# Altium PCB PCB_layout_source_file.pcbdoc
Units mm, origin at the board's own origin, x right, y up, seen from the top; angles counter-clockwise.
Board outline 87.02 x 77.5 mm, 2 copper layers (Top Layer, Bottom Layer); 64 components, 31 nets, 166 pads, 66 vias.
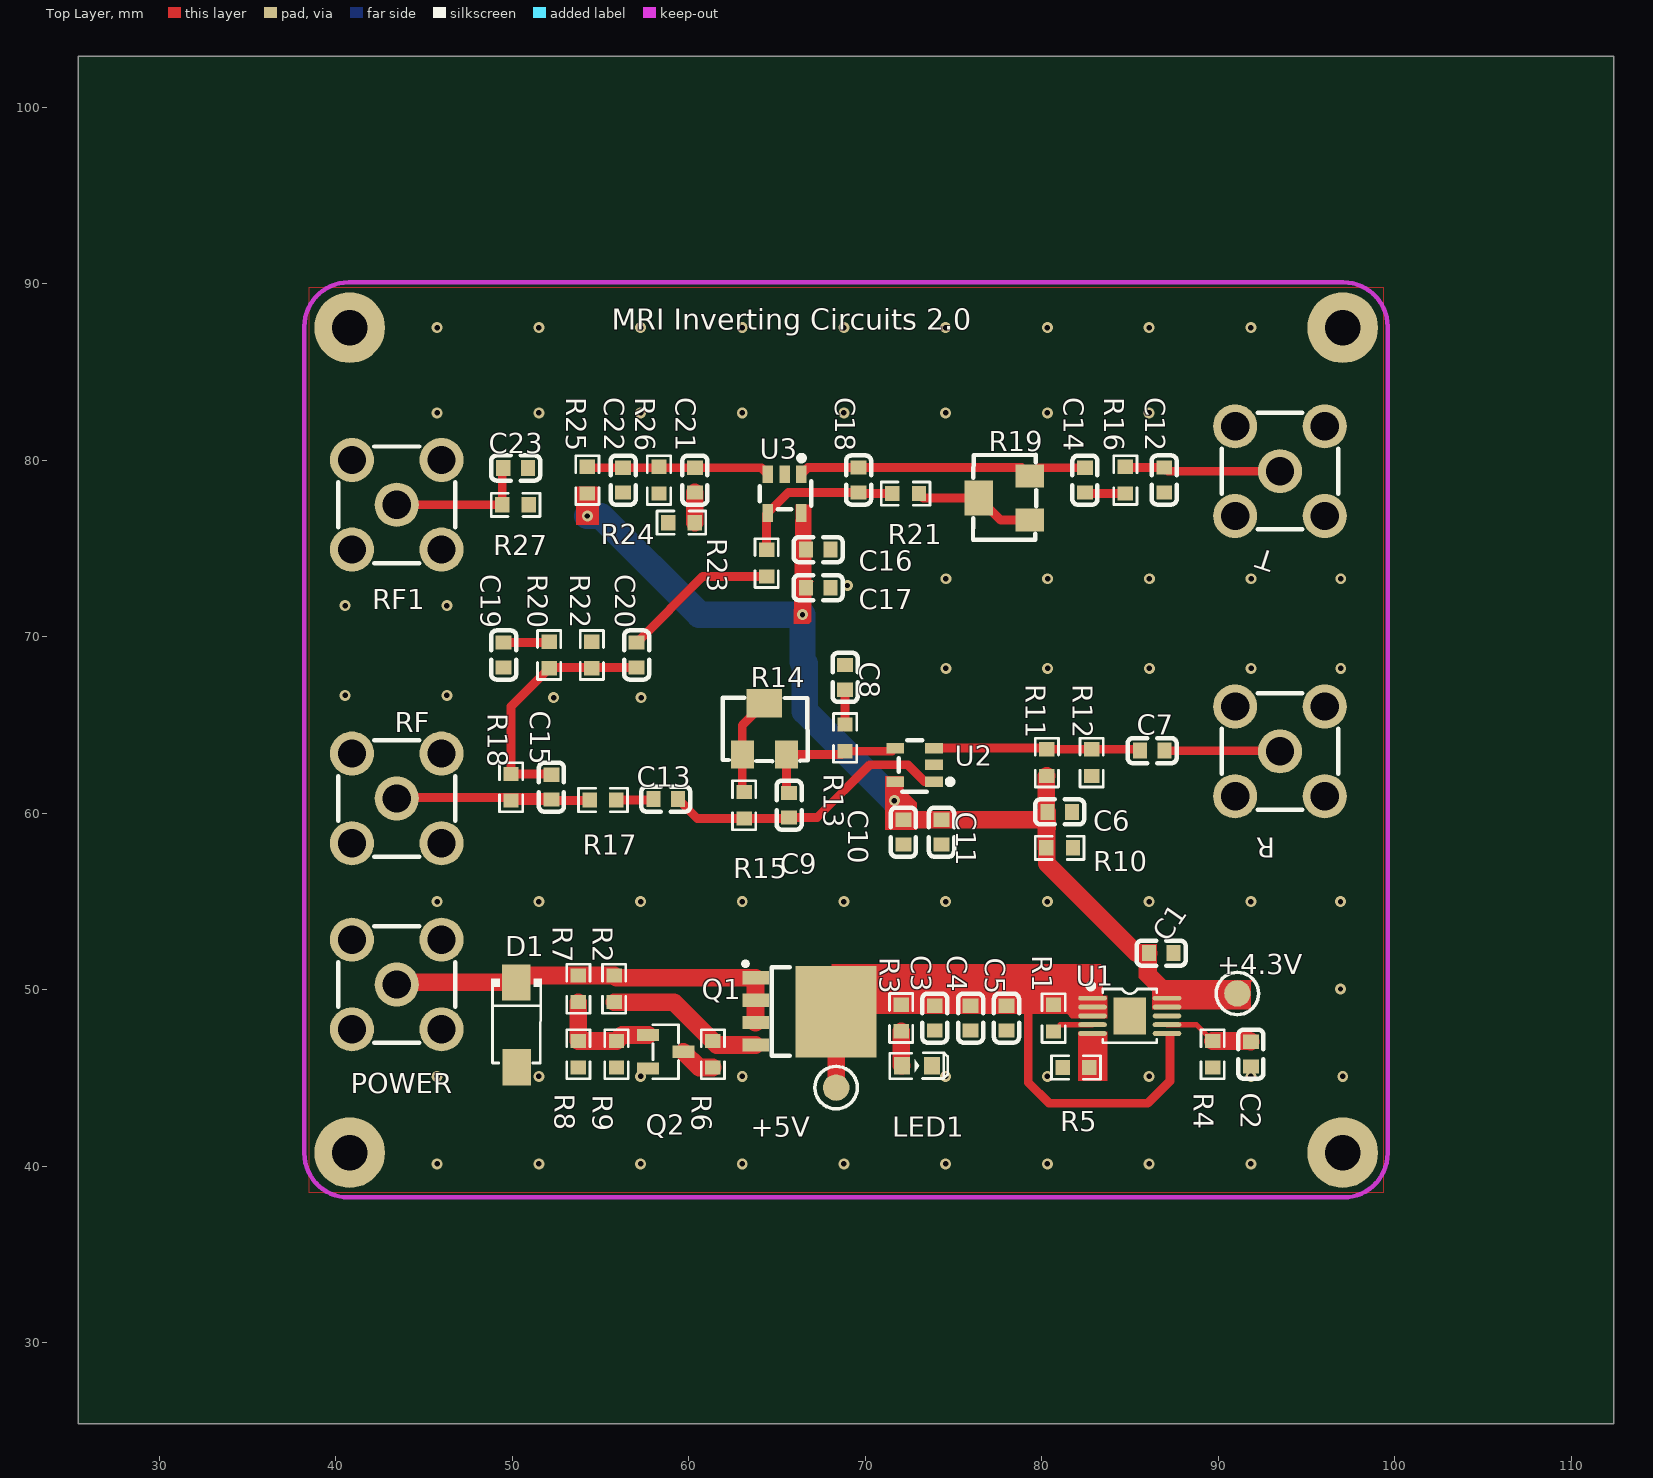
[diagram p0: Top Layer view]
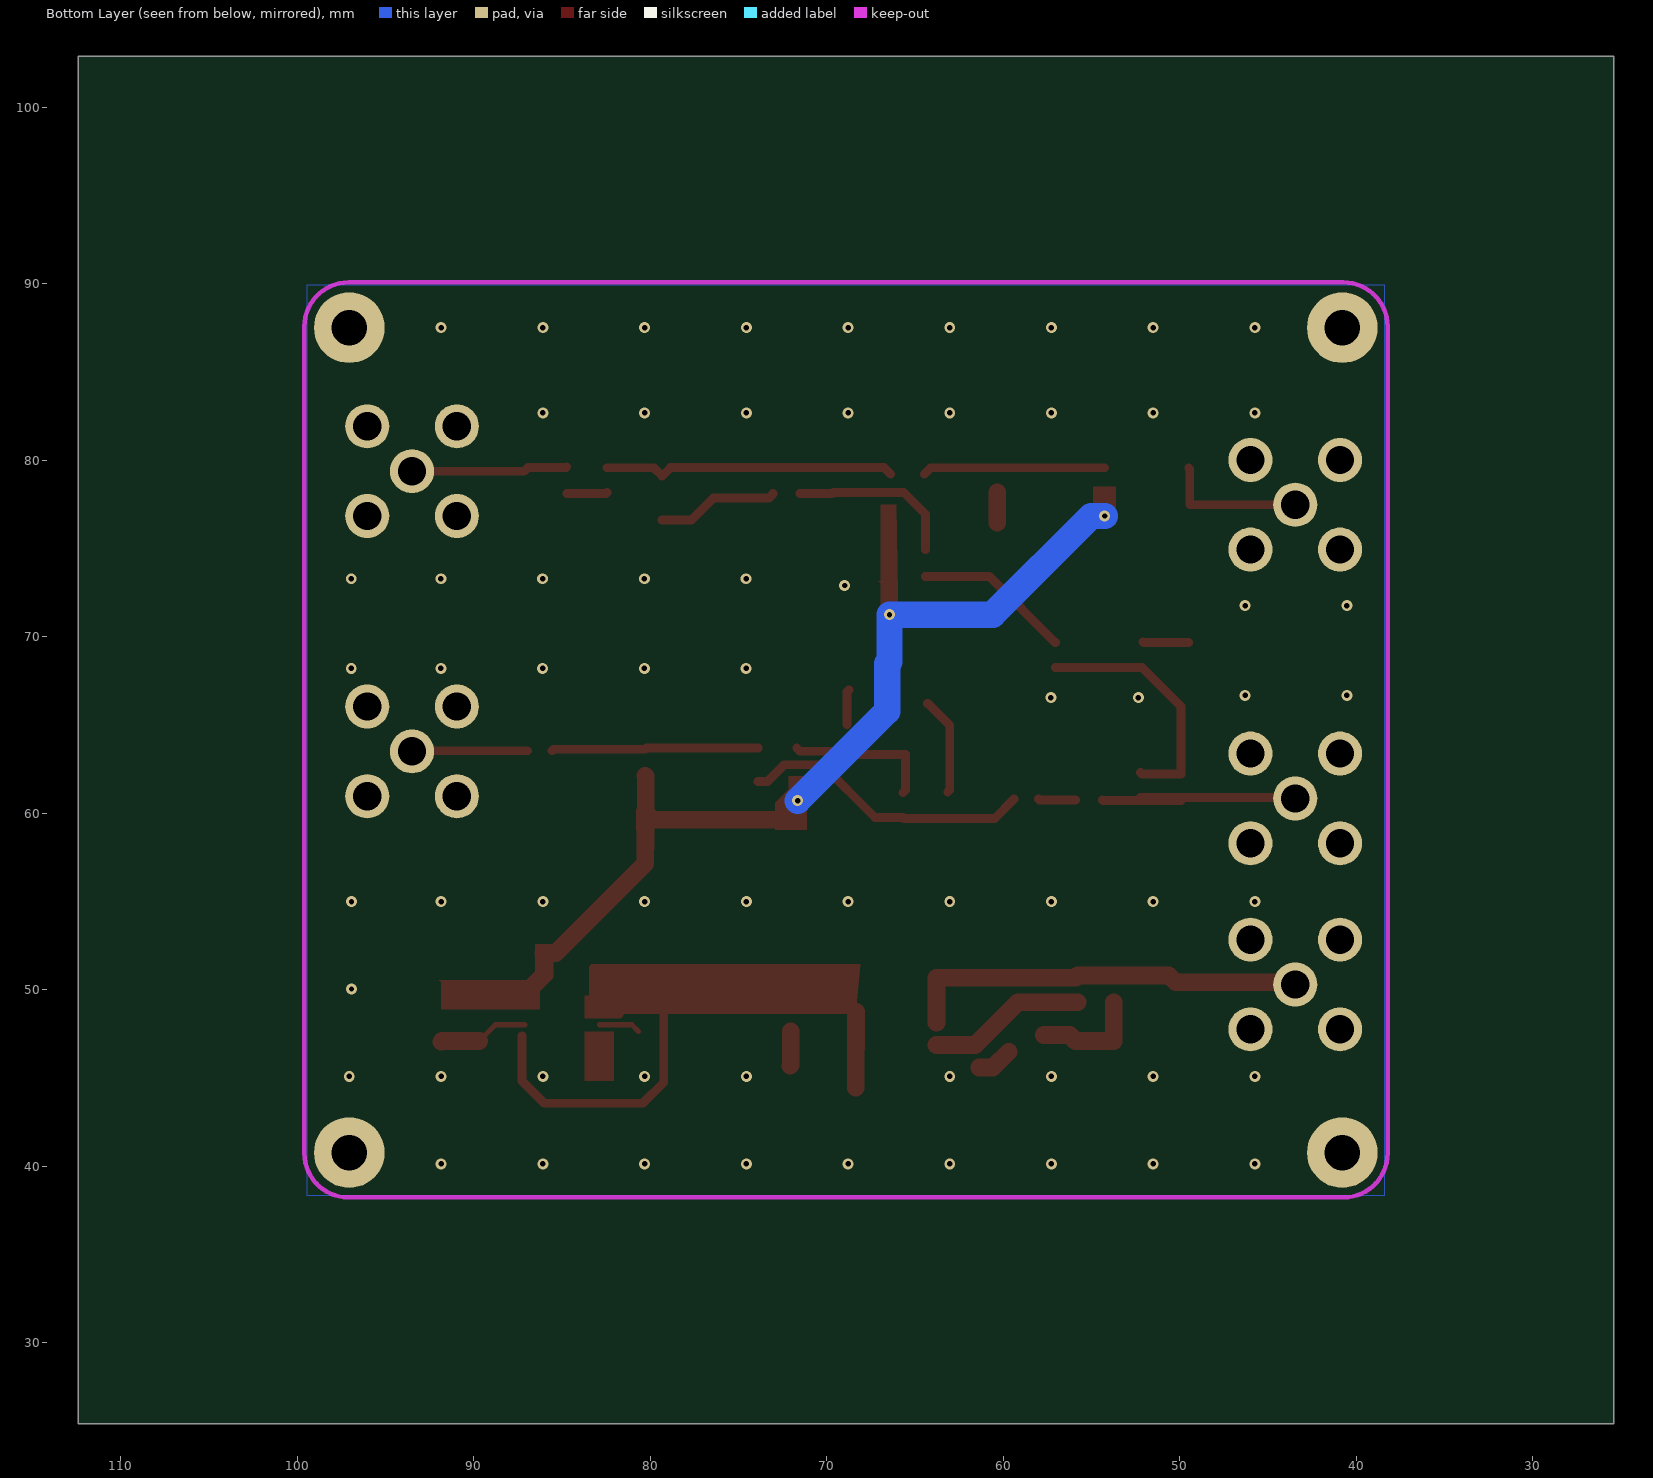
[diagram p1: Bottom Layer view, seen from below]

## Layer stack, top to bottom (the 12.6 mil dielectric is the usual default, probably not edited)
Top Layer: signal copper (thickness not stored)
Dielectric: dielectric 0.32, FR-4, Dk 4.8
Bottom Layer: signal copper (thickness not stored)

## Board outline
112.421,25.4 25.4,25.4 25.4,102.896 112.421,102.896

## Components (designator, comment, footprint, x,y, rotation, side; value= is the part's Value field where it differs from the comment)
+4.3V "TP" TP_2MM 90.957,50.038 r0 top
+5V "TP" TP_2MM 68.224,44.704 r0 top
C1 "陶瓷电容,CAP MC,16V,4.7uF,±10%,X7R,0603,SMD" C0603 86.766,52.07 r0 top
C2 "陶瓷电容,CAP MC,16V,4.7uF,±10%,X7R,0603,SMD" C0603 91.846,46.346 r90 top
C3 "陶瓷电容,CAP MC,25V,4.7uF,±10%,X7R,0603,SMD" C0603 73.939,48.392 r90 top
C4 "陶瓷电容,CAP MC,50V,100nF,±10%,X7R,0603,SMD" C0603 75.971,48.392 r90 top
C5 "陶瓷电容,CAP MC,50V,1nF,±10%,X7R,0603,SMD" C0603 78.003,48.392 r90 top
C6 "10u" C0603 81.019,60.071 r180 top
C7 "0.1u" C0603 86.258,63.54 r180 top
C8 "0.1u" C0603 68.859,67.691 r90 top
C9 "0.1u" C0603 65.684,60.452 r270 top
C10 "0.1u" C0603 72.161,58.928 r270 top
C11 "0.1u" C0603 74.32,58.928 r270 top
C12 "10p" C0603 86.938,78.875 r90 top
C13 "0.1u" C0603 58.699,60.793 r180 top
C14 "100n" C0603 82.448,78.867 r90 top
C15 "0.1u" C0603 52.222,61.473 r90 top
C16 "0.1u" C0603 67.335,74.93 r0 top
C17 "0.1u" C0603 67.335,72.771 r0 top
C18 "0.1u" C0603 69.621,78.875 r270 top
C19 "0.1u" C0603 49.515,68.961 r270 top
C20 "0.1u" C0603 57.048,68.961 r270 top
C21 "10p" C0603 60.35,78.867 r90 top
C22 "0.47u" C0603 56.286,78.867 r90 top
C23 "陶瓷电容,CAP MC,50V,0.1uF,±10%,X7R,0603,SMD" C0603 50.195,79.555 r180 top
D1 "SMAJ54A" SMA_L4.3-W2.6-LS5.0-RD 50.245,48.006 r270 top
LED1 "LED-0603_R" LED0603_RED 72.923,45.686 r0 top
POWER "KH-SMA-KE-Z" SMA-TH_KH-SMA-KE-Z 43.459,50.292 r0 top
Q1 "SQJ479EP-T1_GE3" POWER-SO8_L4.9-W4.4-P1.27-LS6.2-BL 66.065,48.768 r270 top
Q2 "2N7002L" SOT-23-3_L2.9-W1.3-P1.90-LS2.4-BR 58.699,46.482 r180 top
R "KH-SMA-KE-Z" SMA-TH_KH-SMA-KE-Z 93.497,63.5 r0 top
R1 "厚膜电阻,RES,1/10W,200Kohm,±1%,0603,SMD" R0603 80.67,48.387 r90 top
R2 "厚膜电阻,RES,1/10W,120Kohm,±1%,0603,SMD" R0603 55.778,50.048 r90 top
R3 "厚膜电阻,RES,1/10W,51Kohm,±1%,0603,SMD" R0603 72.034,48.397 r90 top
R4 "厚膜电阻,RES,1/10W,43Kohm,±1%,0603,SMD" R0603 89.687,46.341 r90 top
R5 "厚膜电阻,RES,1/10W,1Kohm,±1%,0603,SMD" R0603 81.94,45.593 r0 top
R6 "厚膜电阻,RES,1/10W,12Kohm,±1%,0603,SMD" R0603 61.366,46.341 r90 top
R7 "厚膜电阻,RES,1/10W,200Kohm,±1%,0603,SMD" R0603 53.746,50.048 r90 top
R8 "厚膜电阻,RES,1/10W,10Kohm,±1%,0603,SMD" R0603 53.746,46.341 r90 top
R9 "厚膜电阻,RES,1/10W,434Kohm,±1%,0603,SMD" R0603 55.905,46.341 r270 top
R10 "40k" R0603 81.014,58.039 r180 top
R11 "40k" R0603 80.289,62.865 r270 top
R12 "40k" R0603 82.829,62.865 r90 top
R13 "100" R0603 68.859,64.262 r90 top
R14 "500Ω" RES-ADJ-SMD_3224W 64.287,64.77 r0 top
R15 "50" R0603 63.144,60.452 r270 top
R16 "50" R0603 84.734,78.867 r270 top
R17 "50" R0603 55.143,60.744 r180 top
R18 "1k" R0603 49.936,61.468 r90 top
R19 "500Ω" RES-ADJ-SMD_3224W 77.876,77.851 r90 top
R20 "100" R0603 52.095,68.961 r90 top
R21 "50" R0603 72.288,78.105 r180 top
R22 "100" R0603 54.508,68.961 r90 top
R23 "100" R0603 64.414,74.168 r270 top
R24 "56" R0603 59.588,76.454 r0 top
R25 "40k" R0603 54.254,78.867 r270 top
R26 "40k" R0603 58.318,78.867 r90 top
R27 "厚膜电阻,RES,1/10W,1Kohm,±1%,0603,SMD" R0603 50.19,77.47 r180 top
RF "KH-SMA-KE-Z" SMA-TH_KH-SMA-KE-Z 43.459,60.833 r0 top
RF1 "KH-SMA-KE-Z" SMA-TH_KH-SMA-KE-Z 43.459,77.47 r0 top
T "KH-SMA-KE-Z" SMA-TH_KH-SMA-KE-Z 93.497,79.375 r0 top
U1 "LT3042IMSE#TRPBF" MSOP-10_L3.0-W3.0-P0.50-LS5.0-BL-EP 84.988,48.514 r270 top
U2 "LMH6629MFX/NOPB" SOT-23-5_L2.9-W1.6-P0.95-LS2.8-BR 72.796,62.738 r0 top
U3 "LMH6629MFX/NOPB" SOT-23-5_L2.9-W1.6-P0.95-LS2.8-BR 65.43,78.105 r90 top

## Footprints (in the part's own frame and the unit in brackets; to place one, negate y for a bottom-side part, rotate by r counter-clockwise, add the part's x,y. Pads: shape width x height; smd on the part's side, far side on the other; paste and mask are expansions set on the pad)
C0603 [mm]
  rect 0.8x0.9 smd paste+0 mask+0.051: 1(-0.7,0) 2(0.7,0)
  silkscreen extent -1.39,-0.71 1.39,0.71
LED0603_RED [mm]
  rect 0.9x1 smd paste+0 mask+0.051: 1(-0.85,0) 2(0.85,0)
  silkscreen extent -1.54,-0.73 1.75,0.73
MSOP-10_L3.0-W3.0-P0.50-LS5.0-BL-EP [mm]
  oval 0.28x1.62 smd paste-100 mask+0.051: 1(-1,-2.11) 2(-0.5,-2.11) 3(0,-2.11) 4(0.5,-2.11) 5(1,-2.11) 6(1,2.11) 7(0.5,2.11) 8(0,2.11) 9(-0.5,2.11) 10(-1,2.11)
  rect 2.1x1.83 smd paste-100 mask+0.051: 11(0,0)
  silkscreen extent -1.84,-2.35 1.52,1.52
POWER-SO8_L4.9-W4.4-P1.27-LS6.2-BL [mm]
  rect 0.75x1.5 smd paste+0 mask+0.051: 1(-1.905,-2.279) 2(-0.635,-2.279) 3(0.635,-2.279) 4(1.905,-2.279)
  rect 5.2x4.6 smd paste+0 mask+0.051: 5(0.023,2.28)
  silkscreen extent -2.82,-2.97 2.5,-0.35
R0603 [mm]
  rect 0.806x0.864 smd paste-100 mask+0.051: 1(-0.753,0) 2(0.753,0)
  silkscreen extent -1.39,-0.66 1.39,0.66
RES-ADJ-SMD_3224W [mm]
  rect 1.3x1.6 smd paste+0 mask+0.051: 1(-1.25,-1.45) 3(1.25,-1.45)
  rect 2x1.6 smd paste+0 mask+0.051: 2(0,1.45)
  silkscreen extent -2.36,-1.82 2.47,1.77
SMA-TH_KH-SMA-KE-Z [mm]
  round 2.5 hole 1.6 paste+0 mask+0.051: 1(-2.54,-2.54) 2(-2.54,2.54) 3(2.54,2.54) 4(2.54,-2.54) 5(0,0)
  silkscreen extent -3.3,-3.3 3.3,3.3
SMA_L4.3-W2.6-LS5.0-RD [mm]
  rect 2.046x1.62 smd paste+0 mask+0.051: 1(-2.404,-0.009) 2(2.404,0.009)
  silkscreen extent -2.61,-1.44 2.16,1.44
SOT-23-3_L2.9-W1.3-P1.90-LS2.4-BR [mm]
  rect 1.25x0.7 smd paste+0 mask+0.051: 1(1,-0.95) 2(1,0.95) 3(-1,0)
  silkscreen extent -0.73,-1.53 0.73,1.53
SOT-23-5_L2.9-W1.6-P0.95-LS2.8-BR [mm]
  rect 1x0.6 smd paste+0 mask+0.05: 1(1.1,-0.95) 2(1.1,0) 3(1.1,0.95) 4(-1.1,0.95) 5(-1.1,-0.95)
  silkscreen extent -0.89,-1.52 2.16,1.4
TP_2MM [mm]
  round 1.5 smd paste+0 mask+0.051: 1(0.127,-0.254)
  silkscreen extent -1.07,-1.45 1.33,0.95

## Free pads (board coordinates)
  round 4 hole 2 paste+0 mask+0.051: ""(40.792,40.767) ""(40.792,87.503) ""(97.053,40.767) ""(97.053,87.503)

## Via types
v1: diameter 0.62, hole 0.31, Top Layer to Bottom Layer, tented both sides, 66 vias

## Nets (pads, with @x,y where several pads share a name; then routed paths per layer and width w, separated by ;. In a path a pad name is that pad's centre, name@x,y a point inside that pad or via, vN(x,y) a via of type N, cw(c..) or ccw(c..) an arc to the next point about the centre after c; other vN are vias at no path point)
4V3_STB: +4.3V.1 C1.1 C6.2 C10.1 C11.1 C16.1 C17.1 R10.2 R11.2 R25.2 U1.9 U1.10 U2.5 U3.5 | length 50.4
  Top Layer w1: C10.1 C11.1 79.876,59.628 80.319,60.071 80.289,58.011 80.289,57.15 85.369,52.07 C1.1 ; R10.2@80.26,58.039 80.26,62.083 R11.2
  Bottom Layer w1.5: v1(54.254,76.835) 55.016,76.835 60.604,71.247 v1(66.446,71.247) 66.446,68.587 66.573,68.46 66.573,65.786 v1(71.653,60.706)
5V_STB: +5V.1 C3.2 C4.2 C5.2 Q1.5 R1.2 R3.2 U1.1 U1.2 U1.3 U1.6 | length 20.3
  Top Layer w0.5: 79.24,49.149 79.24,44.737 80.416,43.561 86.004,43.561 87.274,44.831 87.274,47.371
  Top Layer w1: Q1.5 +5V.1
C2_2: C2.2 R4.2 U1.7 | length 5.1
  Top Layer w0.3: U1.7 88.767,48.014 R4.2
  Top Layer w1: R4.2 91.798,47.094 C2.2
C7_2: C7.2 R11.1 R12.2 U2.3 | length 11.7
  Top Layer w0.5: U2.3 80.22,63.688 R11.1 R12.2 85.48,63.618 C7.2
C13_2: C13.2 R17.1 | length 2.1
  Top Layer w0.5: R17.1 57.95,60.744 C13.2
C14_1: C14.1 R16.2 | length 2.3
  Top Layer w0.5: C14.1 82.501,78.114 R16.2
C20_1: C20.1 R23.2 | length 8.9
  Top Layer w0.5: C20.1 60.802,73.415 R23.2
GND: C1.2 C2.1 C3.1 C4.1 C5.1 C6.1 C8.2 C10.2 C11.2 C12.1 C16.2 C17.2 C19.2 C22.1 C23.1 D1.2 LED1.2 pad. POWER.1 POWER.2 POWER.3 POWER.4 Q2.2 R4.1 R5.1 R9.2 R10.1 R12.1 R22.2 R24.1 R26.1 R27.1 R.1 R.2 R.3 R.4 RF1.1 RF1.2 RF1.3 RF1.4 RF.1 RF.2 RF.3 RF.4 T.1 T.2 T.3 T.4 U1.8 U1.11 U2.2 U3.2
  other v1: 45.745,40.132 51.508,40.132 57.27,40.132 63.033,40.132 68.796,40.132 74.558,40.132 80.321,40.132 86.084,40.132 91.846,40.132 45.745,45.085 51.508,45.085 57.27,45.085 63.033,45.085 74.558,45.085 80.321,45.085 86.084,45.085 91.846,45.085 97.053,45.085 96.926,50.038 45.745,54.991 51.508,54.991 57.27,54.991 63.033,54.991 68.796,54.991 74.558,54.991 80.321,54.991 86.084,54.991 91.846,54.991 96.926,54.991 52.349,66.548 57.302,66.548 40.538,66.675 46.301,66.675 74.574,68.199 80.337,68.199 86.099,68.199 91.862,68.199 96.942,68.199 40.538,71.755 46.301,71.755 68.986,72.898 74.574,73.279 80.337,73.279 86.099,73.279 91.862,73.279 96.942,73.279 45.745,82.677 51.508,82.677 57.27,82.677 63.033,82.677 68.796,82.677 74.558,82.677 80.321,82.677 86.084,82.677 45.745,87.503 51.508,87.503 57.27,87.503 63.033,87.503 68.796,87.503 74.558,87.503 80.321,87.503 86.084,87.503 91.846,87.503
PS_STB: D1.1 POWER.5 Q1.1 Q1.2 Q1.3 R2.2 R7.2 | length 23.1
  Top Layer w1: POWER.5@43.522,50.292 43.639,50.41 50.235,50.41 50.627,50.802 R2.2 55.907,50.673 Q1.1 Q1.3
R1_1: R1.1 U1.4 | length 2.4
  Top Layer w0.3: R1.1 81.05,48.014 U1.4
R2_1: Q1.4 R2.1 R6.2 | length 9
  Top Layer w1: R2.1 59.165,49.295 R6.2 61.597,46.863 Q1.4
R3_1: LED1.1 R3.1 | length 2
  Top Layer w1: R3.1 72.034,45.725 LED1.1
R5_2: R5.2 U1.5
R6_1: Q2.3 R6.1 | length 2
  Top Layer w1: Q2.3 60.594,45.588 R6.1
R8_2: Q2.1 R7.1 R8.2 R9.1 | length 6.3
  Top Layer w1: R7.1 R8.2 R9.1 56.243,47.432 Q2.1
R13_2: C8.1 R13.2 | length 2
  Top Layer w0.5: C8.1@68.732,66.991 68.859,66.864 R13.2
R15_1: R14.1 R14.2 R15.1 | length 5.6
  Top Layer w0.5: R15.1 63.037,61.312 R14.1 63.037,64.97 R14.2
R16_1: C12.2 R16.1 T.5 | length 8.9
  Top Layer w0.5: R16.1 84.779,79.575 C12.2 87.138,79.375 T.5
R17_2: C15.1 R17.2 R18.1 RF.5 | length 15.6
  Top Layer w0.5: RF.5 43.52,60.895 52.222,60.895 52.042,60.715 R18.1 54.361,60.715 R17.2
R18_2: C15.2 C20.2 R18.2 R20.1 R22.1 | length 14.2
  Top Layer w0.5: C15.2@52.222,62.295 52.148,62.221 R18.2 49.936,66.049 R20.1 52.148,68.261 C20.2
R20_2: C19.1 R20.2 | length 2.6
  Top Layer w0.5: C19.1 52.042,69.661 R20.2
R21_1: R19.1 R19.2 R21.1 | length 6.9
  Top Layer w0.5: R21.1 73.295,77.851 R19.2 77.676,76.601 R19.1
R23_1: C18.2 R21.2 R23.1 U3.4 | length 9.7
  Top Layer w0.5: R23.1 64.414,76.939 U3.4 65.65,78.175 C18.2 69.691,78.105 R21.2
R24_2: C21.1 R24.2 | length 1.7
  Top Layer w1: R24.2@60.342,76.454 C21.1
R_5: C7.1 R.5 | length 6.6
  Top Layer w0.5: C7.1 93.41,63.54 R.5@93.497,63.627
RF1_5: C23.2 R27.2 RF1.5 | length 8.2
  Top Layer w0.5: RF1.5@43.459,77.851 43.84,77.47 R27.2 49.437,79.497 C23.2
S$1142: 
U2_1: C9.2 C13.1 R15.2 U2.1 | length 16.6
  Top Layer w0.5: C13.1 60.493,59.699 R15.2 65.631,59.699 C9.2 ; C9.2 67.269,59.751 70.256,62.738 72.415,62.738 73.365,61.788 U2.1
U2_4: C9.1 R13.1 R14.3 U2.4 | length 8.5
  Top Layer w0.5: C9.1 65.537,61.299 R14.3 68.67,63.32 R13.1 71.516,63.509 U2.4
U3_1: C14.2 C18.1 R19.3 U3.1 | length 16.6
  Top Layer w0.5: U3.1 66.75,79.575 C18.1 78.852,79.575 R19.3 79.792,79.567 C14.2
U3_3: C21.2 C22.2 R25.1 R26.2 U3.3 | length 10.4
  Top Layer w0.5: R25.1@54.254,79.567 64.118,79.567 U3.3
pads on no net: R8.1

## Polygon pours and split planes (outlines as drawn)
GND on Bottom Layer (solid): 38.379,89.916 99.466,89.916 99.466,38.354 38.379,38.354
GND on Top Layer (solid): 38.506,89.789 99.339,89.789 99.339,38.481 38.506,38.481
GND on Top Layer (solid): 38.506,89.789 99.339,89.789 99.339,38.481 38.506,38.481

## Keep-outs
Keep-Out Layer:
  lines w0.254: 38.227,40.727 ccw(c40.727,40.727) 40.727,38.227 ; 38.227,87.569 cw(c40.727,87.569) 40.727,90.069 ; 97.094,38.227 ccw(c97.094,40.727) 99.594,40.727 ; 97.094,90.069 cw(c97.094,87.569) 99.594,87.569

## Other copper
Top Layer:
  region net R5_2: 82.067,47.625 83.718,47.625 83.718,44.831 82.067,44.831
  region net 4V3_STB: 66.065,77.47 66.954,77.47 66.954,77.343 66.954,70.866 66.827,70.739 65.938,70.739
  region net 5V_STB: 68.344,48.745 68.449,48.641 80.035,48.641 80.162,48.768 83.718,48.768 83.464,49.022 83.464,51.308 83.337,51.435 68.097,51.435
  region net 4V3_STB: 66.192,73.152 67.081,73.152 66.954,73.025 66.954,70.866 66.192,70.866 66.192,70.993
  region net 4V3_STB: 53.619,78.486 54.889,78.486 54.889,76.327 53.619,76.327
  region net 4V3_STB: 71.145,62.103 72.161,62.103 72.161,61.341 72.923,60.579 72.923,59.055 71.145,59.055
  region net 4V3_STB: 86.258,48.895 91.846,48.895 91.846,50.419 91.973,50.546 87.02,50.546 86.512,51.054 86.512,52.578 85.496,52.578 85.496,51.181 85.496,50.673 86.258,49.911 86.258,48.895
  region net 5V_STB: 83.718,48.387 83.718,49.657 79.527,49.657 79.527,48.641 81.432,48.641 81.686,48.387 82.067,48.387 81.94,48.387

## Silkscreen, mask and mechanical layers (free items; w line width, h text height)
Top Overlay:
  text "MRI Inverting Circuits 2.0" at 55.651,86.995 h2.03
